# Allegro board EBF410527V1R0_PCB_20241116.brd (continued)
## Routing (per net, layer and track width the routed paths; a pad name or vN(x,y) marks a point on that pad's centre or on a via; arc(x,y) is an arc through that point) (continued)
VCC3V3_SD: length 8.9
  TOP w0.305: 19.44,46.79 20.02,47.37 21.36,47.37 21.98,47.99 R15.2 ; 19.44,46.79 19.44,46.83 18.9,47.37 17.45,47.37 16.9,46.82 C11.1 16.14,47.49 J2.4 ; 19.44,46.79 C10.1
VCC5V0_SYS: length 50.6
  TOP w0.254: v1(52.73,43.71) 52.82,43.81 U3.65 ; U3.66 v1(51.73,43.71) ; v1(69.81,12.27) 69.86,12.32 R12.1
  TOP w0.381: U17.6 65.53,47.09 65.91,47.47 67.23,47.47 67.61,47.09 67.61,43.65 C53.1 68.46,41.69 C52.1 v1(69.84,41.19)
  GND02 w0.254: v1(29.11,5.64) 29.11,7.19
  GND02 w0.508: J12.2 75.56,3.25 ; J12.2 74.56,2.25 ; J12.2 76.57,2.25 ; J12.4 74.03,2.25 ; J12.4 72.02,2.25 ; J12.4 73.03,3.25
  BOTTOM w0.254: R8.1 29.08,5.61 v1(29.11,5.64) ; v1(5.42,33.25) 5.84,33.67 5.84,48.64 6.53,49.33 16.59,49.33 C2.1 R6.1
  vias: v1(4.42,33.25) v1(4.42,32.25) v1(4.42,31.25) v1(4.45,27.96) v1(4.45,26.96) v1(4.45,25.96) v1(5.44,27.96) v1(51.73,42.71) v1(52.73,42.71) v1(67.54,51.51) v1(67.54,50.71) v1(67.54,49.91) v1(68.54,51.51) v1(69.84,41.99) v1(69.84,40.39) v1(70.64,41.19) v1(72.35,7.3) v1(73.35,7.3) v1(74.35,7.3) v1(75.35,9.3) v1(75.35,8.3) v1(75.35,7.3)
VCC_1V8: length 100.7
  TOP w0.254: 51.45,41.57 v1(51.45,31.72) ; 51.45,41.57 49.52,43.49 U3.68 ; 51.45,41.57 52.01,42.14 55.5,42.14 v1(56.57,41.07) ; v1(70.74,32) 70.74,32.26 72.13,33.65 v1(72.13,34.95) 72.14,34.96 72.14,36.65 70.64,38.15 70.64,39.67 71.31,40.35 71.31,42.19 70.48,43.02 70.48,44.04 69.47,45.06 R79.1 R80.1 ; R94.2 79.38,49.28 v1(82.42,49.28)
  GND02 w0.254: v1(72.13,34.95) 69.69,37.39 63.07,37.39 61.09,39.37 60.25,39.37 59.66,39.95 58.7,39.95 57.58,41.07 v1(56.57,41.07)
  BOTTOM w0.203: C12.1 47.11,33.51 U4.12
  BOTTOM w0.254: R33.1 v1(51.45,31.72) ; R33.1 50.77,30.63 R35.1 51.51,29.89 51.51,28.02 R22.1 ; R33.1 R31.1 R29.1 50.18,34.59 48.19,34.59 C12.1 ; v1(70.74,32) 73.53,32 74.17,31.37 81.15,31.37 82.42,32.64 v1(82.42,49.28)
VCC_3V3: length 239.2
  TOP w0.254: R74.1 v1(18.57,3.29) ; R75.1 v1(18.87,16.26)
  TOP w0.305: R15.1 C9.1 v1(23.75,49.15)
  TOP w0.508: J12.17 56.47,6.01 59.25,6.01 59.72,6.48 59.72,9.5 60.07,9.86 61.75,9.86 62.18,10.29 62.18,12.42 62.66,12.9 64.18,12.9
  GND02 w0.254: 20.52,6.53 25.7,6.53 26.64,5.59 26.64,2.18 27.07,1.76 v1(27.22,1.76) ; 20.52,6.53 19.58,5.59 19.58,3.71 19.17,3.29 v1(18.57,3.29) ; 20.52,6.53 19.43,7.62 19.43,15.71 v1(18.87,16.26) 13.58,16.26 13.03,16.81 13.03,18.47 12.57,18.92 2.21,18.92 1.7,19.43 1.7,36.17 2.34,36.8 v1(4.98,36.8)
  GND02 w0.381: v1(25.55,31.25) 22.32,31.25 v1(20.17,33.41) 18.05,33.41 14.66,36.8 v1(4.98,36.8)
  BOTTOM w0.203: C13.1 46.71,33.88 U4.11 ; C1.1 38.25,33.37 U1.9 ; C14.1 46.46,27.29 U5.21
  BOTTOM w0.254: v1(41.04,21.45) C19.1 R45.1 ; R36.1 v1(42.7,30.58) ; C13.1 v1(46.58,34.8) ; R64.1 R65.1 23.88,49.28 v1(23.75,49.15) ; C7.1 68.08,13.67 C8.1 R10.1 C5.1 ; v1(49.78,29.08) R28.1 R27.1 ; v1(47.75,29.08) 47.53,29.08 47.17,28.73 47.17,28 C14.1 ; R30.1 v1(42.7,34.01) 39.9,34.01 R1.1 39.29,34.62 38.16,34.62 C1.1 ; R9.1 32.55,4.94 33.12,4.37 33.12,2.46 32.84,2.18 27.64,2.18 v1(27.22,1.76) ; R34.1 v1(42.7,31.72) ; R32.1 v1(42.7,32.87) ; R26.1 v1(43.43,29.08)
  BOTTOM w0.305: v1(4.98,36.8) 4.98,49.15 5.89,50.06 21.56,50.06 22.17,49.45 23.44,49.45 v1(23.75,49.15)
  BOTTOM w0.381: 32.12,27.41 32.12,24.6 31.32,23.8 ; 32.12,27.41 J4.24 ; 32.12,27.41 C33.1 32.14,28.89 32.56,29.31 34.47,29.31 35.23,30.07 35.23,34.26 34.8,34.7 31.97,34.7 31.46,35.2 v1(31.46,36.25) ; J4.2 30.94,15.41 31.32,15.79 31.32,23.8 ; 31.32,23.8 30.86,24.26 28.32,24.26 25.55,27.03 v1(25.55,31.25) ; C35.1 32.14,37.62 C34.1 32.01,38.61 J4.52 ; J4.39 v1(20.17,33.41)
  BOTTOM w0.508: v1(65.37,14.73) 65.37,8.78 66.42,7.72 70.71,7.72 71.98,6.45 73.9,6.45 J12.1
  vias: v1(31.45,37.2) v1(65.37,16.33) v1(65.37,15.53) v1(66.17,16.33) v1(66.17,15.53) v1(66.17,14.73) v1(70.13,34.95) v1(70.13,33.95) v1(71.13,34.95) v1(71.13,33.95)
VCC_3V3_EN: length 52.6
  TOP w0.152: U3.70 47.33,43.28 47.6,43 48.84,43 49.96,41.88 49.96,30.89 51.16,29.69 51.16,20.77 v1(51.92,20.01) ; R14.1 69.86,16.76 v1(69.57,17.04)
  BOTTOM w0.152: v1(51.92,20.01) 52.82,20.9 69.37,20.9 69.57,20.7 v1(69.57,17.04)
VCC_WLAN: length 8.7
  TOP w0.508: U10.6 62.32,32.09 62,32.41 62,35.3 62.51,35.81 C28.1 ; C29.1 C28.1 ; C28.1 63.13,35.81 Q2.3
VDD_LCD_3V3: length 30.9
  TOP w0.254: v1(23.77,48.13) 24.87,48.13 26.59,49.86 26.59,53.82 27.38,54.61 46.38,54.61 47.66,53.33
  BOTTOM w0.254: R63.1 24.31,47.24 23.77,47.78 v1(23.77,48.13)
  vias: v1(48.11,53.05) v1(49.06,53.05)
VDD_LCD_5V:
  vias: v1(49.05,52.12) v1(49.06,51.16)
CAM0_NRST: length 58.2
  TOP w0.152: v1(66.22,30.02) 66.76,29.48 66.76,24.74 66.45,24.43 62.14,24.43 60.76,23.05 v1(60.76,22.58)
  BOTTOM w0.152: v1(60.76,22.58) 51.97,22.58 50.41,24.14 U5.2 ; J5.22 49.47,48.18 49.77,47.88 52.02,47.88 52.27,48.13 52.73,48.13 53.06,47.8 53.06,46.34 54.76,44.64 54.76,42.3 55.21,41.86 55.21,38.34 57.1,36.44 57.1,34.09 58.33,32.86 58.33,31.57 60.61,29.29 62.26,29.29 62.99,30.02 v1(66.22,30.02)
CAM0_PWDN: length 56.1
  TOP w0.152: v1(67.22,30.02) 67.22,24.53 66.66,23.98 62.33,23.98 61.73,23.38 61.73,22.61 v1(61.76,22.58)
  BOTTOM w0.152: v1(61.76,22.58) 61.68,22.58 61.2,23.06 52.25,23.06 50.67,24.64 U5.1 ; J5.15 52.97,48.58 53.52,48.03 53.52,46.53 55.22,44.83 55.22,42.52 55.66,42.07 55.66,38.53 57.56,36.63 57.56,34.28 58.79,33.05 58.79,31.76 60.78,29.77 62.03,29.77 62.87,30.61 66.63,30.61 v1(67.22,30.02)
CAM0_PWR_EN: length 8.7
  TOP w0.152: U3.59 60.95,42.16 62.28,43.48 66.13,43.48 v1(66.19,43.42)
  BOTTOM w0.152: v1(66.19,43.42) 66.59,43.81 R59.1
CAM1_NRST: length 40
  TOP w0.152: v1(46.57,37.44) 46.57,36.91 46.09,36.43 46.09,34.6 46.38,34.31 46.38,29.87 47.27,28.98 47.27,25.63 49.58,23.32 v1(49.58,23.14)
  BOTTOM w0.152: U5.4 v1(49.58,23.14) ; J6.22 31.27,48.67 31.58,48.36 33.68,48.36 35.48,46.56 35.48,42.43 39.94,37.98 46.04,37.98 v1(46.57,37.44)
CAM1_PWDN: length 40.6
  TOP w0.152: v1(50.58,23.14) 50.58,29.38 50.16,29.79 48.01,29.79 47.5,30.3 47.5,31.85 46.84,32.51 46.84,33.99 47.57,34.72 v1(47.57,37.44)
  BOTTOM w0.152: J6.15 34.77,48.03 35.97,46.84 35.97,42.6 40.13,38.43 46.58,38.43 v1(47.57,37.44) ; v1(50.58,23.14) 50.08,23.64 U5.3
CAM1_PWR_EN: length 18.1
  TOP w0.152: U3.58 57.84,41.06 57.53,41.36 57.53,43.48 58.14,44.09 58.14,47.19 57.86,47.47 57.15,47.47 56.97,47.65 v1(52.52,47.65)
  BOTTOM w0.152: v1(52.52,47.65) 52.3,47.42 49.21,47.42 R61.1
DBG_DN: length 68.1
  TOP w0.157: v1(36.78,32.36) 37.63,32.36 37.97,32.7 37.97,34.26 38.81,35.11 v1(38.81,35.59)
  BOTTOM w0.157: U1.7 37.11,32.05 36.8,32.36 v1(36.78,32.36) ; v1(38.81,35.59) 39.09,35.86 50.62,35.86 52.47,34.02 52.47,25.15 53.11,24.51 72.52,24.51 72.9,24.13 72.9,19.34 73.42,18.82 76.05,18.82 76.71,18.16 76.71,16.13 77.6,15.24 77.6,12.57 78.03,12.14 79.74,12.14 80.07,11.81 R3.2
DBG_DP: length 70.4
  TOP w0.157: v1(38.81,36.55) 38.81,36.3 39.31,35.8 39.31,35.09 38.33,34.11 38.33,32.7 38.64,32.38 v1(39.52,32.38)
  BOTTOM w0.157: U1.1 39.36,32.05 39.52,32.21 v1(39.52,32.38) ; R2.2 80.07,12.83 79.74,12.5 78.18,12.5 77.96,12.72 77.96,15.39 77.07,16.28 77.07,18.31 76.2,19.18 73.57,19.18 73.26,19.49 73.26,24.28 72.67,24.87 53.26,24.87 52.83,25.3 52.83,34.17 50.77,36.23 44.4,36.23 arc(44.31,36.26) 44.28,36.35 arc(44.24,36.44) 44.15,36.47 43.77,36.47 arc(43.68,36.44) 43.65,36.35 arc(43.61,36.26) 43.52,36.23 43.14,36.23 arc(43.05,36.26) 43.02,36.35 arc(42.98,36.44) 42.89,36.47 42.51,36.47 arc(42.42,36.44) 42.39,36.35 arc(42.35,36.26) 42.26,36.23 41.88,36.23 arc(41.79,36.26) 41.76,36.35 arc(41.72,36.44) 41.63,36.47 41.25,36.47 arc(41.16,36.44) 41.13,36.35 arc(41.09,36.26) 41,36.23 40.62,36.23 arc(40.53,36.26) 40.5,36.35 arc(40.46,36.44) 40.37,36.47 39.99,36.47 arc(39.91,36.44) 39.87,36.35 arc(39.83,36.26) 39.74,36.23 39.14,36.23 v1(38.81,36.55)
DBG_RX: length 4.3
  TOP w0.152: R89.1 Z2.1 73.19,45.44 73.69,45.44 74.17,44.96 J13.2
DBG_TX: length 3.4
  TOP w0.152: Z1.1 R88.1 76.71,45.98 J13.3
DC_EN: length 3.8
  TOP w0.152: R14.2 R12.2 71.31,12.63 U2.1
DISP: length 8.5
  TOP w0.152: v1(26.59,47.22) 26.62,47.24 30.11,47.24 31.21,48.34 31.95,48.34 32.52,48.9 J7.7
  BOTTOM w0.152: v1(26.59,47.22) 26.57,47.24 R63.2
DM1: length 10.4
  TOP w0.157: R37.1 17.46,27.61 17.46,28.47 17.53,28.54 U9.2 U9.9 17.53,30.64 17.46,30.71 17.46,31.03 17.1,31.39 16.22,31.39 15.75,30.92 15.75,28.83 15.41,28.49 14.32,28.49 J3.2
DM2: length 16.2
  TOP w0.157: R40.1 18.96,28.14 18.96,28.47 19.03,28.54 U9.5 U9.6 19.03,30.64 18.96,30.71 18.96,31.25 17.88,32.33 15.39,32.33 14.76,31.71 14.76,30.89 14.6,30.73 12.47,30.73 11.99,30.25 11.99,28.8 11.68,28.49 11.32,28.49 J3.8
DP1: length 10.4
  TOP w0.157: R38.1 17.1,28.14 17.1,28.47 17.03,28.54 U9.1 U9.10 17.03,30.64 17.1,30.71 17.1,30.88 16.95,31.03 16.37,31.03 16.11,30.77 16.11,28.68 15.56,28.13 13.81,28.13 13.5,27.83 J3.3
DP2: length 15.6
  TOP w0.157: R42.1 18.6,27.61 18.6,28.47 18.53,28.54 U9.4 U9.7 18.53,30.64 18.6,30.71 18.6,31.1 17.73,31.97 15.53,31.97 15.12,31.56 15.12,30.74 14.75,30.37 12.62,30.37 12.35,30.1 12.35,28.65 11.83,28.13 10.83,28.13 10.5,27.8 J3.9
FEPHY_LINK: length 40
  TOP w0.152: U3.102 21.67,31.15 21.06,30.55 21.06,28.3 20.57,27.81 20.57,24.23 20.24,23.9 20.24,12.62 v1(19.96,12.34)
  GND02 w0.152: v1(19.96,12.34) 20.45,11.86 20.45,8.81 21.95,7.32 26.21,7.32 27.28,6.25 28.04,6.25 28.57,5.71 28.57,4.39 28.9,4.07 v1(31.68,4.07)
  BOTTOM w0.152: R78.1 31.55,3.95 v1(31.68,4.07)
FEPHY_RXN: length 37.5
  TOP w0.124: v1(51.81,7.68) 52.11,7.98 52.11,8.39 51.73,8.78 U3.25
  BOTTOM w0.124: v1(51.81,7.68) 52.11,7.98 52.11,8.27 52.43,8.59 53.25,8.59 53.57,8.27 53.57,7.34 53.12,6.89 51.14,6.89 50.61,6.35 47.6,6.35 47.3,6.65 24.32,6.65 23.87,7.1 23.14,7.1 22.8,6.76 R70.1
FEPHY_RXP: length 35.9
  TOP w0.124: U3.26 52.82,8.81 52.44,8.42 52.44,7.98 v1(52.74,7.68)
  BOTTOM w0.124: v1(52.74,7.68) 52.69,7.68 52.44,7.93 52.44,8.13 52.56,8.26 53.11,8.26 53.24,8.13 53.24,7.47 52.98,7.21 51.01,7.21 50.47,6.68 47.74,6.68 47.43,6.98 24.45,6.98 24.01,7.43 23.14,7.43 22.8,7.77 R71.1
FEPHY_SPD: length 35
  TOP w0.152: U3.103 22.17,30.06 21.54,29.42 21.54,28.07 20.88,27.41 20.88,24.08 20.55,23.75 20.55,11.93 v1(19.96,11.34)
  GND02 w0.152: v1(28.08,4.07) 27.51,4.65 27.51,5.54 26.09,6.96 21.82,6.96 20.09,8.69 20.09,11.22 v1(19.96,11.34)
  BOTTOM w0.152: R76.1 27.95,3.95 v1(28.08,4.07)
FEPHY_TXN: length 38.5
  TOP w0.124: v1(49.81,7.68) 49.47,7.35 49.47,6.89 49.68,6.68 55.09,6.68 55.41,7.01 55.41,8.1 55.29,8.23 55.15,8.23 55.03,8.35 U3.28
  BOTTOM w0.124: R72.1 22.8,9.8 23.14,9.46 24.02,9.46 25.16,8.32 46.67,8.32 46.86,8.51 49.16,8.51 49.47,8.19 49.47,7.93 49.72,7.68 v1(49.81,7.68)
FEPHY_TXP: length 39
  TOP w0.124: v1(48.81,7.68) 49.15,7.35 49.15,6.75 49.55,6.35 55.22,6.35 55.74,6.87 55.74,8.1 55.86,8.23 56,8.23 56.13,8.35 U3.29
  BOTTOM w0.124: v1(48.81,7.68) 48.9,7.68 49.15,7.93 49.15,8.05 49.02,8.18 46.99,8.18 46.81,7.99 25.03,7.99 23.89,9.13 23.14,9.13 22.8,8.79 R73.1
GPIO0_A0: length 60.1
  TOP w0.152: v1(35.14,13.18) 34.65,13.67 34.65,16.28 29.67,21.25 U3.111
  BOTTOM w0.152: v1(35.14,13.18) 42.09,13.18 43.64,14.73 59.28,14.73 59.94,14.07 59.94,6.76 61.44,5.26 61.44,3.86 61.65,3.66 66.82,3.66 J12.7
GPIO0_A1: length 52.1
  TOP w0.152: v1(34.14,14.18) 34.14,15.77 29.76,20.15 U3.112
  BOTTOM w0.152: J12.11 62.5,4.79 60.3,6.99 60.3,14.3 59.56,15.04 43.32,15.04 41.97,13.69 34.63,13.69 v1(34.14,14.18)
GPIO0_A2: length 49.9
  TOP w0.152: v1(34.14,13.18) 33.48,13.84 33.48,15.37 29.79,19.06 U3.113
  BOTTOM w0.152: J12.13 59.61,5.5 59.61,13.74 58.93,14.43 43.92,14.43 42.19,12.7 34.62,12.7 v1(34.14,13.18)
GPIO0_A4: length 51
  TOP w0.152: v1(30.64,12.12) 30.64,16.04 29.83,16.85 U3.115
  BOTTOM w0.152: v1(30.64,12.12) 30.64,11.4 30.96,11.07 32.26,11.07 32.89,11.71 43.21,11.71 44.22,12.73 48.84,12.73 49.93,13.82 58.55,13.82 58.95,13.41 58.95,5.95 J12.15
GPIO0_A5: length 54.3
  TOP w0.152: U3.116 24.7,15.76 25.25,16.31 29.34,16.31 29.64,16 v1(29.64,12.12)
  BOTTOM w0.152: J12.16 59.28,3.74 59.28,13.54 58.7,14.12 49.81,14.12 48.94,13.26 44.07,13.26 42.9,12.09 32.59,12.09 32,11.51 31.46,11.51 31.16,11.81 31.16,12.35 30.91,12.6 30.12,12.6 v1(29.64,12.12)
GPIO5_P1_0: length 28.3
  TOP w0.152: v1(53.7,11.18) 51.4,13.48 51.4,19.45 50.92,19.93 v1(50.92,20.01)
  BOTTOM w0.152: J12.18 56.34,3.34 56.34,11.35 56.03,11.66 54.18,11.66 v1(53.7,11.18) ; v1(50.92,20.01) 46.61,20.01 46.46,20.16 U5.10
GPIO5_P1_1: length 29.8
  TOP w0.152: v1(51.92,19.01) 51.92,13.96 v1(54.7,11.18)
  BOTTOM w0.152: U5.11 45.96,19.79 46.27,19.49 51.44,19.49 v1(51.92,19.01) ; v1(54.7,11.18) 55.4,10.48 55.4,6.55 54.2,5.36 54.2,3.66 53.9,3.35 52.22,3.35 51.12,2.25 J12.22
GPIO5_P1_2: length 34.3
  TOP w0.152: v1(50.92,19.01) 50.92,12.96 v1(52.7,11.18)
  BOTTOM w0.152: v1(50.92,19.01) 45.77,19.01 45.46,19.31 U5.12 ; J12.26 45.88,2.25 46.91,3.28 48.49,3.28 48.92,3.71 51.05,3.71 51.51,4.17 51.51,5.56 51.82,5.87 53.54,5.87 54.56,6.88 54.56,9.7 54.25,10.01 53.07,10.01 52.7,10.38 v1(52.7,11.18)
HUB_3V3: length 17
  BOTTOM w0.254: R41.1 R39.1 R43.1 41.15,27.68 41.15,25.03 C21.1 ; U6.1 39.5,20.47 39.73,20.24 40.5,20.24 41.32,19.42 C20.1 42.39,20.03 42.39,22.88 R45.2 C21.1 ; C21.1 41.16,24.39 40.91,24.14 U6.20
I2C3_SCL_LT: length 85.6
  TOP w0.152: v1(45.11,31.78) 44.45,31.11 v1(44.45,29.08)
  GND02 w0.152: v1(45.11,31.78) 44.73,32.16 44.04,32.16 43.64,32.56 43.64,38.43 43.13,38.94 43.13,43.04 v1(42.54,43.64)
  BOTTOM w0.152: J6.6 39.27,48.51 40.36,47.42 40.36,45.03 41.74,43.65 42.52,43.65 v1(42.54,43.64) ; J12.5 69.33,5.94 62.43,5.94 61.75,6.63 61.75,12.03 62.06,12.33 63.8,12.33 64.11,12.64 64.11,17.35 62.18,19.28 60.43,19.28 59.36,18.21 44.17,18.21 43.87,18.52 43.87,25.53 42.49,26.9 42.49,29.72 42.19,30.02 42.19,30.96 42.42,31.2 43.89,31.2 R34.2 44.47,31.78 v1(45.11,31.78) 45.19,31.85 U4.8 ; R23.1 v1(44.45,29.08)
I2C3_SCL_M2: length 22.1
  TOP w0.152: U3.75 41.82,43.42 43.64,41.61 48.06,41.61 48.67,41 48.67,34.34 48.21,33.88 48.21,32.16 v1(49.06,31.31)
  BOTTOM w0.152: R33.2 49.48,31.72 v1(49.06,31.31) 48.92,31.45 U4.3
I2C3_SDA_LT: length 86.4
  GND02 w0.152: v1(45.11,30.78) 45.59,31.26 45.59,32.21 45.16,32.64 44.35,32.64 44.09,32.9 44.09,38.64 43.54,39.19 v1(43.54,43.64)
  BOTTOM w0.152: R36.2 43.88,30.05 43.1,30.05 42.8,29.74 42.8,27.02 44.17,25.65 44.17,18.82 44.48,18.52 59.11,18.52 60.25,19.66 62.23,19.66 64.41,17.47 64.41,12.33 64.11,12.03 62.53,12.03 62.23,11.72 62.23,6.86 62.71,6.38 70.59,6.38 72.18,4.79 J12.3 ; R36.2 44.61,30.78 v1(45.11,30.78) 45.31,30.98 45.31,31.29 45.47,31.45 U4.7 ; R36.2 45.47,29.53 R24.1 ; J6.5 39.77,48.49 40.69,47.57 40.69,45.19 41.64,44.23 42.94,44.23 v1(43.54,43.64)
I2C3_SDA_M2: length 25.5
  TOP w0.152: U3.76 40.73,43.55 43.13,41.15 47.7,41.15 48.23,40.61 48.23,34.57 47.19,33.53 47.19,32.79 47.9,32.08 47.9,30.74 48.34,30.31 v1(49.06,30.31)
  BOTTOM w0.152: U4.4 47.11,30.64 47.26,30.49 48.88,30.49 v1(49.06,30.31) 49.36,30.61 R35.2
I2C4_SCL_LT: length 162.9
  TOP w0.152: v1(45.54,51.95) 45.67,52.08 45.67,53.44 45.21,53.9 30.73,53.9 30.3,53.47 30.3,51.48 29.52,50.7 J7.1 ; J12.28 43.63,3.33 61.47,3.33 61.77,3.63 61.77,6.38 61.27,6.88 v1(61.27,6.92) ; v1(60.78,17.77) 61.26,18.25 61.26,20.47 63.02,22.23 68.63,22.23 68.94,22.53 68.94,29.28 v1(69.66,30)
  BOTTOM w0.152: v1(61.27,6.92) 60.76,7.43 60.76,12.74 61.06,13.04 63.18,13.04 63.5,13.36 63.5,17.1 62.82,17.77 v1(60.78,17.77) 60.76,17.77 60.54,17.55 43.79,17.55 43.26,18.08 43.26,25.27 41.88,26.64 41.88,29.08 41.43,29.54 41.43,33.15 41.76,33.48 43.88,33.48 R30.2 45.03,33.4 46.1,33.4 46.31,33.19 U4.10 ; v1(69.66,30) 69.17,29.51 68.4,29.51 66.8,31.11 62.59,31.11 62.15,31.55 62.15,43.4 61.61,43.94 60.55,43.94 59.72,44.78 59.72,46.33 57.47,48.57 J5.6 57.47,50.19 57.32,50.34 45.47,50.34 45.14,50.68 45.14,51.55 v1(45.54,51.95)
I2C4_SCL_M2: length 18.9
  TOP w0.152: U3.72 45.12,42.77 45.43,42.47 48.74,42.47 49.5,41.71 49.5,33.75 v1(49.06,33.31)
  BOTTOM w0.152: U4.1 48,32.25 48.26,32.51 48.26,33.02 48.55,33.31 v1(49.06,33.31) R29.2
I2C4_SDA_LT: length 154.9
  TOP w0.152: J12.27 43.62,3.71 61.05,3.71 61.35,4.01 61.35,5.88 60.79,6.45 60.79,7.43 v1(61.27,7.92) ; v1(68.66,30) 68.53,29.87 68.53,22.83 68.22,22.53 62.79,22.53 60.78,20.52 v1(60.78,18.77) ; v1(45.62,50.95) 45.06,51.51 45.06,52.3 45.26,52.5 45.26,53.24 44.96,53.54 31.06,53.54 30.68,53.16 30.68,51.29 30.02,50.62 J7.2
  BOTTOM w0.152: U4.9 45.42,32.25 45.21,32.46 44.82,32.46 R32.2 43.86,32.31 42.11,32.31 41.81,32 41.81,29.79 42.19,29.41 42.19,26.77 43.56,25.4 43.56,18.29 43.99,17.86 59.84,17.86 60.76,18.77 v1(60.78,18.77) 62.26,18.77 63.8,17.22 63.8,13.04 63.46,12.7 61.57,12.7 61.27,12.4 v1(61.27,7.92) ; v1(45.62,50.95) 45.9,50.67 57.82,50.67 57.97,50.52 J5.5 57.97,48.55 60.17,46.35 60.17,44.91 60.68,44.4 61.72,44.4 62.6,43.52 62.6,31.91 62.92,31.6 67.06,31.6 v1(68.66,30)
I2C4_SDA_M2: length 20.2
  TOP w0.152: U3.73 44.03,42.32 44.33,42.01 48.39,42.01 49.05,41.35 49.05,34.06 48.54,33.55 48.54,32.83 v1(49.06,32.31)
  BOTTOM w0.152: R31.2 49.62,32.87 v1(49.06,32.31) 48.61,31.85 U4.2
LCD_INT: length 61.2
  TOP w0.152: J7.3 30.52,49.23 29.96,48.67 27.33,48.67 v1(27.08,48.92) ; U3.6 30.82,10.59 31.13,10.9 32.99,10.9 33.83,11.73 36.17,11.73 36.6,12.17 36.6,16.87 30.56,22.91 30.56,30.65 30.25,30.96 v1(26.94,30.96)
  BOTTOM w0.152: R65.2 26.72,49.28 v1(27.08,48.92) 27.43,48.57 27.43,45.9 29.35,43.98 29.83,43.98 30.14,43.66 30.14,43.01 30.71,42.44 30.71,40.16 30.35,39.8 27.58,39.8 27.28,39.49 27.28,31.3 v1(26.94,30.96)
LCD_PWM_BL: length 60.5
  TOP w0.152: v1(25.98,46.53) 25.98,47.47 26.29,47.78 30.17,47.78 31.09,48.69 31.7,48.69 32.02,49.01 J7.6 ; v1(26.07,37.76) 26.37,37.46 26.37,29.77 26.67,29.46 29.31,29.46 29.62,29.16 29.62,22.2 35.71,16.1 35.71,12.9 35.41,12.6 33.45,12.6 32.49,11.63 29.62,11.63 28.63,10.64 U3.4
  GND02 w0.152: v1(26.07,37.76) 26.07,37.81 25.35,38.53 23.37,38.53 22.94,38.96 22.94,41.12 24.71,42.9 24.71,44.48 25.98,45.75 v1(25.98,46.53)
LCD_RST: length 61.1
  TOP w0.152: v1(26.94,29.96) 29.79,29.96 30.1,29.65 30.1,22.58 36.12,16.56 36.12,12.47 35.81,12.17 33.63,12.17 32.72,11.25 30.3,11.25 29.73,10.68 U3.5 ; J7.4 31.02,49.05 30.23,48.26 v1(26.39,48.26)
  BOTTOM w0.152: R64.2 v1(26.39,48.26) 27.1,47.55 27.1,45.77 29.14,43.73 29.14,43.1 30.35,41.88 30.35,40.46 30,40.1 27.33,40.1 26.95,39.72 26.95,32.08 26.42,31.55 26.42,30.48 v1(26.94,29.96)
LINEOUT: length 56.1
  TOP w0.203: U3.89 v1(26.42,43.66) ; v1(32.27,51) 32.27,52.24 32.94,52.91 43.74,52.91 44.27,52.37 44.27,51.28 v1(44.63,50.93) ; C54.1 64.27,39.44 63.58,40.13 63.58,42.24 v1(63.32,42.49)
  GND02 w0.203: v1(26.42,43.66) 26.53,43.66 27.34,44.48 28.32,44.48 28.65,44.81 28.65,49.33 30.86,51.54 31.74,51.54 v1(32.27,51) ; v1(63.32,42.49) 62.31,42.49 60.99,43.81 59.21,43.81 57.28,45.75 56.79,45.75 54.84,47.7 53.77,47.7 52.55,48.92 46.94,48.92 46.18,49.68 45.16,49.68 44.63,50.22 v1(44.63,50.93)
MICIN0_N: length 78.9
  TOP w0.203: C50.2 R83.1 ; C50.2 v1(74.56,47.75) ; C50.2 74.83,48.79 74.83,49.21 73.8,50.24 J9.2
  TOP w0.254: U3.96 v1(25.07,37.76)
  GND02 w0.203: v1(25.07,37.76) 24.78,37.47 23.37,37.47 22.32,38.52 22.32,41.34 24.1,43.12 24.1,44.78 25.17,45.85 25.17,46.81 25.87,47.51 25.87,48.48 27.99,50.6 27.99,52.78 28.4,53.19 32.36,53.19 32.91,53.74 49.33,53.74 50.9,52.17 55.6,52.17 59.11,48.67 59.11,46.71 60.02,45.8 68.45,45.8 70.79,48.13 74.18,48.13 v1(74.56,47.75)
MICIN0_P: length 81
  TOP w0.203: C50.1 v1(75.56,47.75) ; C50.1 75.23,48.84 75.23,49.35 75.05,49.54 J9.1 ; C50.1 R81.1
  TOP w0.254: U3.97 v1(25.07,36.65)
  GND02 w0.203: v1(25.07,36.65) 25.07,36.66 24.66,37.07 23.21,37.07 21.92,38.35 21.92,41.5 23.7,43.28 23.7,44.91 24.8,46.01 24.8,47 25.52,47.72 25.52,48.63 27.64,50.74 27.64,52.93 28.29,53.59 32.22,53.59 32.74,54.1 49.48,54.1 51,52.58 55.7,52.58 59.46,48.82 59.46,46.88 60.19,46.15 68.28,46.15 70.62,48.49 74.82,48.49 v1(75.56,47.75)
MICIN1_N: length 73.5
  TOP w0.203: J10.2 64.95,49.06 C51.2 ; C51.2 R84.1 ; C51.2 63.84,47.96 62.05,47.96 61.03,46.93 v1(60.82,46.93)
  TOP w0.254: U3.99 v1(25.55,34.46)
  GND02 w0.203: v1(60.82,46.93) 61.03,47.14 61.03,47.71 60.4,48.34 60.4,49.69 56.5,53.59 51.59,53.59 50.44,54.74 32.11,54.74 31.65,54.28 27.61,54.28 26.87,53.54 26.87,50.98 24.79,48.9 24.79,47.93 24.1,47.24 24.1,46.33 23.09,45.31 23.09,43.56 21.31,41.78 21.31,37.44 24.61,34.14 25.34,34.14 25.55,34.35 v1(25.55,34.46)
MICIN1_P: length 75.6
  TOP w0.203: J10.1 66.2,50.22 65.4,49.42 C51.1 ; C51.1 64.48,47.6 62.37,47.6 61.82,47.04 v1(61.82,46.93) ; C51.1 R82.1
  TOP w0.254: U3.100 v1(25.55,33.36)
  GND02 w0.203: v1(25.55,33.36) 25.55,33.46 25.23,33.78 24.47,33.78 20.95,37.29 20.95,41.93 22.73,43.71 22.73,45.49 23.72,46.48 23.72,47.36 24.41,48.05 24.41,49.05 26.49,51.14 26.49,53.7 27.45,54.66 31.49,54.66 31.92,55.1 50.59,55.1 51.71,53.98 56.64,53.98 60.76,49.86 60.76,48.49 61.41,47.84 61.41,47.34 v1(61.82,46.93)
MIPI_CSI_RX_CLK0N: length 22.7
  TOP w0.124: U3.49 59.78,31.15 60.19,31.56 60.67,31.56 v1(60.92,31.31)
  BOTTOM w0.124: v1(60.92,31.31) 60.62,31.61 60.28,31.61 59.64,32.26 59.64,33.4 58.41,34.63 58.41,42.45 57.23,43.64 57.23,45.06 55.56,46.73 55.56,48.52 55.47,48.61 J5.10
MIPI_CSI_RX_CLK0P: length 22.7
  TOP w0.124: U3.50 59.82,32.25 60.19,31.89 60.57,31.89 v1(60.92,32.24)
  BOTTOM w0.124: J5.9 55.97,48.61 55.89,48.52 55.89,48.24 arc(55.92,48.17) 55.99,48.14 arc(56.05,48.11) 56.08,48.04 56.08,47.74 arc(56.05,47.67) 55.99,47.64 arc(55.92,47.61) 55.89,47.54 55.89,46.86 56.28,46.47 arc(56.37,46.43) 56.47,46.47 56.47,46.47 arc(56.56,46.51) 56.65,46.47 56.82,46.3 arc(56.86,46.21) 56.82,46.12 arc(56.78,46.02) 56.82,45.93 57.55,45.2 57.55,43.77 58.74,42.59 58.74,34.76 59.97,33.53 59.97,32.39 60.42,31.94 60.67,31.94 60.92,32.19 v1(60.92,32.24)
MIPI_CSI_RX_CLK1N: length 45.3
  TOP w0.124: v1(56.4,25.65) 56.77,25.28 56.77,22.13 57.26,21.64 57.67,21.64 57.8,21.52 57.8,21.38 57.92,21.25 U3.40
  BOTTOM w0.124: v1(56.4,25.65) 56.68,25.94 56.68,27.04 57.12,27.48 58.06,27.48 58.18,27.61 58.18,28.17 58.06,28.3 57.38,28.3 57.02,28.65 57.02,29.49 55.98,30.53 55.98,31.89 54.71,33.16 54.71,35.07 48.69,41.09 40.69,41.09 37.45,44.34 37.45,48.44 37.27,48.61 J6.10
MIPI_CSI_RX_CLK1P: length 45.1
  TOP w0.124: U3.41 57.92,22.36 57.8,22.23 57.8,22.09 57.67,21.97 57.4,21.97 57.1,22.27 57.1,25.33 57.4,25.63 v1(57.4,25.63)
  BOTTOM w0.124: v1(57.4,25.63) 57.35,25.63 57.01,25.97 57.01,26.9 57.26,27.15 58.19,27.15 58.51,27.47 58.51,28.31 58.19,28.63 57.51,28.63 57.35,28.79 57.35,29.62 56.31,30.67 56.31,32.02 55.04,33.29 55.04,35.21 48.82,41.42 40.82,41.42 37.77,44.47 37.77,44.82 arc(37.8,44.89) 37.87,44.92 arc(37.94,44.95) 37.97,45.02 37.97,45.32 arc(37.94,45.39) 37.87,45.42 arc(37.8,45.45) 37.77,45.52 37.77,45.82 arc(37.8,45.89) 37.87,45.92 arc(37.94,45.95) 37.97,46.02 37.97,46.31 arc(37.94,46.39) 37.87,46.41 arc(37.8,46.44) 37.77,46.51 J6.9
MIPI_CSI_RX_D0N: length 22.3
  TOP w0.124: U3.55 58.33,37.76 57.95,38.14 57.5,38.14 57.35,37.99 57.35,35.11 57.03,34.79 56.55,34.79 56.24,35.11 56.24,38.53 56.9,39.19 56.9,39.46 v1(56.6,39.76)
  BOTTOM w0.124: v1(56.6,39.76) 56.9,40.06 56.9,40.47 57.15,40.73 57.15,41.39 56.43,42.12 56.43,42.6 56.21,42.82 56.21,45 54.56,46.65 54.56,48.52 54.47,48.61 J5.12
MIPI_CSI_RX_D0P: length 22.3
  TOP w0.124: v1(57.53,39.76) 57.23,39.46 57.23,39.06 56.57,38.4 56.57,35.24 56.69,35.12 56.9,35.12 57.02,35.24 57.02,38.13 57.36,38.47 57.98,38.47 58.36,38.85 U3.56
  BOTTOM w0.124: J5.11 54.97,48.61 54.89,48.52 54.89,48.23 arc(54.92,48.16) 54.99,48.13 arc(55.06,48.1) 55.09,48.03 55.09,47.73 arc(55.06,47.66) 54.99,47.63 arc(54.92,47.6) 54.89,47.53 54.89,46.79 56.54,45.14 56.54,44.68 arc(56.58,44.59) 56.67,44.56 arc(56.76,44.52) 56.79,44.43 56.79,44.19 arc(56.76,44.1) 56.67,44.06 arc(56.58,44.02) 56.54,43.93 56.54,42.95 56.76,42.73 56.76,42.25 57.48,41.53 57.48,40.59 57.23,40.34 57.23,40.06 v1(57.53,39.76)
MIPI_CSI_RX_D1N: length 22.5
  TOP w0.124: v1(60.92,34.61) 60.67,34.86 60.13,34.86 59.73,34.46 U3.52
  BOTTOM w0.124: v1(60.92,34.61) 60.62,34.91 59.88,34.91 59.44,35.35 59.44,37.67 59.88,38.12 60.43,38.12 60.58,38.27 60.58,38.49 60.46,38.61 59.88,38.61 59.44,39.05 59.44,40.81 59.88,41.25 60.43,41.25 60.58,41.4 60.58,41.63 60.46,41.75 59.85,41.75 59.54,42.07 59.54,42.95 58.22,44.27 58.22,45.99 56.56,47.65 56.56,48.52 56.47,48.61 J5.8
MIPI_CSI_RX_D1P: length 22.5
  TOP w0.124: v1(60.92,35.54) 60.57,35.19 60.19,35.19 59.82,35.55 U3.53
  BOTTOM w0.124: v1(60.92,35.54) 60.62,35.24 60.01,35.24 59.76,35.49 59.76,37.54 60.01,37.79 60.57,37.79 60.91,38.13 60.91,38.62 60.59,38.94 60.01,38.94 59.76,39.19 59.76,40.68 60.01,40.93 60.57,40.93 60.91,41.27 60.91,41.76 60.59,42.08 59.99,42.08 59.87,42.2 59.87,43.09 58.54,44.41 58.54,44.95 arc(58.58,45.03) 58.66,45.07 arc(58.74,45.1) 58.78,45.18 58.78,45.45 arc(58.74,45.53) 58.66,45.56 arc(58.58,45.6) 58.54,45.68 58.54,46.13 57.86,46.81 arc(57.82,46.9) 57.86,46.98 arc(57.89,47.06) 57.86,47.15 57.67,47.33 arc(57.59,47.37) 57.51,47.33 arc(57.42,47.3) 57.34,47.33 56.89,47.79 56.89,48.52 56.97,48.61 J5.7
MIPI_CSI_RX_D2N: length 44.7
  TOP w0.124: v1(56.04,27.94) 56.34,28.24 57.67,28.24 57.8,28.12 57.8,27.98 57.92,27.85 U3.46
  BOTTOM w0.124: J6.12 36.27,48.61 36.36,48.52 36.36,47.76 36.65,47.46 36.65,43.13 40.01,39.78 48.58,39.78 53.59,34.77 53.59,30.63 53.91,30.31 54.74,30.31 54.87,30.19 54.87,29.94 54.74,29.81 53.91,29.81 53.59,29.5 53.59,26.73 54.06,26.26 54.87,26.26 55.24,26.63 55.24,28.01 55.48,28.24 55.74,28.24 v1(56.04,27.94)
MIPI_CSI_RX_D2P: length 44.7
  TOP w0.124: U3.47 57.92,28.95 57.8,28.83 57.8,28.69 57.67,28.57 56.34,28.57 v1(56.04,28.87)
  BOTTOM w0.124: v1(56.04,28.87) 55.74,28.57 55.34,28.57 54.91,28.14 54.91,26.77 54.74,26.59 54.2,26.59 53.92,26.87 53.92,29.36 54.05,29.48 54.88,29.48 55.19,29.8 55.19,30.32 54.88,30.64 54.05,30.64 53.92,30.76 53.92,34.9 48.72,40.11 40.14,40.11 38.79,41.46 arc(38.75,41.54) 38.79,41.62 arc(38.82,41.7) 38.79,41.78 38.59,41.97 arc(38.51,42.01) 38.43,41.97 arc(38.35,41.94) 38.27,41.97 38.08,42.17 arc(38.05,42.25) 38.08,42.33 arc(38.12,42.41) 38.08,42.49 37.89,42.68 arc(37.81,42.71) 37.73,42.68 arc(37.65,42.64) 37.57,42.68 36.98,43.27 36.98,47.6 36.69,47.89 36.69,48.52 36.77,48.61 J6.11
MIPI_CSI_RX_D3N: length 44.7
  TOP w0.124: v1(61.92,27.79) 61.62,27.49 61.62,25.38 61.18,24.94 60.48,24.94 60.35,24.82 60.35,24.68 60.23,24.55 U3.43
  BOTTOM w0.124: J6.8 38.27,48.61 38.36,48.52 38.36,47.57 39.18,46.74 39.18,44.43 41.37,42.24 49.11,42.24 56.02,35.33 56.02,33.7 57.29,32.43 57.29,31.08 59.32,29.05 59.32,27.17 59.97,26.52 61.2,26.52 61.62,26.94 61.62,27.49 v1(61.92,27.79)
MIPI_CSI_RX_D3P: length 44.6
  TOP w0.124: v1(60.99,27.79) 61.29,27.49 61.29,25.52 61.04,25.27 60.48,25.27 60.35,25.39 60.35,25.53 60.23,25.66 U3.44
  BOTTOM w0.124: v1(60.99,27.79) 61.04,27.79 61.29,27.54 61.29,27.08 61.06,26.85 60.1,26.85 59.65,27.3 59.65,29.19 57.62,31.22 57.62,32.57 56.35,33.84 56.35,35.46 49.25,42.57 43.86,42.57 arc(43.79,42.6) 43.76,42.67 arc(43.73,42.74) 43.66,42.77 43.37,42.77 arc(43.29,42.74) 43.26,42.67 arc(43.23,42.6) 43.16,42.57 42.87,42.57 arc(42.79,42.6) 42.76,42.67 arc(42.73,42.74) 42.66,42.77 42.37,42.77 arc(42.3,42.74) 42.27,42.67 arc(42.24,42.6) 42.16,42.57 41.51,42.57 41.04,43.04 arc(41,43.12) 41.04,43.2 arc(41.07,43.29) 41.04,43.37 40.85,43.56 arc(40.77,43.59) 40.68,43.56 arc(40.6,43.52) 40.52,43.56 40.33,43.74 arc(40.3,43.82) 40.33,43.91 arc(40.37,43.99) 40.33,44.07 40.14,44.26 arc(40.06,44.29) 39.98,44.26 arc(39.9,44.22) 39.81,44.26 39.51,44.56 39.51,44.92 arc(39.54,45) 39.62,45.03 arc(39.69,45.06) 39.73,45.14 39.73,45.42 arc(39.69,45.49) 39.62,45.53 arc(39.54,45.56) 39.51,45.63 39.51,45.92 arc(39.54,45.99) 39.62,46.02 arc(39.69,46.06) 39.73,46.13 39.73,46.41 arc(39.69,46.49) 39.62,46.52 arc(39.54,46.55) 39.51,46.63 39.51,46.88 38.69,47.7 38.69,48.52 38.77,48.61 J6.7
NPOR: length 84.9
  TOP w0.152: v1(27.51,11.43) 26.48,12.45 U3.119 ; R87.1 74.41,32.81 73.25,31.65 73.25,19.02 72.52,18.29 68.44,18.29 v1(68.18,18.03)
  GND02 w0.152: v1(58.45,6.67) 64.07,12.29 68.15,12.29 68.68,12.83 68.68,17.54 v1(68.18,18.03)
  BOTTOM w0.152: v1(27.51,11.43) 28.96,9.98 44.16,9.98 44.9,10.72 48.86,10.72 50.59,12.45 56.85,12.45 57.15,12.14 57.15,8.38 57.66,7.87 57.66,7.46 v1(58.45,6.67)
PWM3_IR_M1: length 12.3
  TOP w0.152: J12.29 40.01,7.54 39.7,7.85 32.97,7.85 32.66,8.15 32.18,8.15 31.93,8.41 U3.7
PWM7_IR_M1: length 37.9
  TOP w0.152: U3.8 33.03,8.48 33.33,8.18 40.89,8.18 41.2,7.87 41.2,1.65 41.63,1.22 61.84,1.22 J12.12
RGB_LCD_EN: length 108.3
  TOP w0.152: U3.117 24.46,14.66 25.7,15.9 28.2,15.9 28.51,15.6 v1(28.51,11.43) ; v1(77.24,41.45) 77.24,33.57 76.94,33.27 74.08,33.27 72.77,31.95 72.77,19.3 72.26,18.8 68,18.8 67.69,18.49 67.69,17.53 v1(68.18,17.03)
  GND02 w0.152: v1(58.45,7.67) 58.7,7.67 63.8,12.78 67.88,12.78 68.18,13.08 v1(68.18,17.03)
  BOTTOM w0.152: v1(77.24,41.45) 78.08,42.29 78.08,45.64 77.7,46.02 75.13,46.02 73.66,47.5 70.48,47.5 69.98,48.01 R67.1 ; v1(28.51,11.43) 29.5,10.44 43.97,10.44 44.71,11.18 48.67,11.18 50.4,12.9 57.3,12.9 57.61,12.6 57.61,8.57 58.45,7.73 v1(58.45,7.67)
S_SET: length 42.8
  TOP w0.152: SW1.1 63.67,17.83 v1(62.87,17.02)
  BOTTOM w0.152: v1(62.87,17.02) 62.64,17.25 43.59,17.25 42.9,17.93 42.9,25.2 41.58,26.52 41.58,28.75 40.97,29.36 40.97,33.12 40.67,33.43 39.48,33.43 R1.2 38.65,33.82 U1.10
SARADC_IN0_REC: length 74.3
  TOP w0.152: v1(77.84,46.93) 78.49,46.29 78.49,41.25 79.5,40.23 R90.1 ; U3.87 v1(28.63,43.56)
  GND02 w0.152: v1(77.84,46.93) 77.36,47.41 76.39,47.41 75.34,46.35 70.15,46.35 68.44,44.64 65.34,44.64 64.57,43.87 63.02,43.87 62.76,44.12 62.76,44.78 62.48,45.06 59.61,45.06 57.94,46.74 57.94,48.39 56.34,49.99 48.18,49.99 47.88,50.29 47.88,52.04 47.11,52.81 45.17,52.81 44.83,52.48 43.28,52.48 42.77,52.98 34.14,52.98 33.76,52.6 33.76,50.47 33.43,50.14 30.4,50.14 29.36,49.1 29.36,44.3 v1(28.63,43.56)
SARADC_IN1: length 67.1
  TOP w0.152: U3.86 29.73,43.59 v1(29.63,43.49) ; v1(76.84,46.93) 77.45,47.54 79.32,47.54 R91.1
  GND02 w0.152: v1(76.84,46.93) 75.86,45.95 70.43,45.95 68.68,44.2 65.58,44.2 64.82,43.43 62.69,43.43 61.39,44.73 59.41,44.73 56.92,47.22 56.92,48.79 56.16,49.56 47.98,49.56 47.5,50.04 47.5,51.79 46.84,52.45 45.26,52.45 44.86,52.04 43.03,52.04 42.5,52.58 35.1,52.58 34.77,52.25 34.77,50.8 33.73,49.76 30.56,49.76 29.67,48.87 29.67,43.54 v1(29.63,43.49)
SDMMC_CLK: length 46
  TOP w0.157: J2.5 13.62,48.59 12.8,47.78 12.8,47.41 12.96,47.26 13.25,47.26 13.41,47.1 13.41,46.78 13.25,46.63 12.96,46.63 12.8,46.47 12.8,46.15 12.96,46 13.25,46 13.41,45.84 13.41,45.52 13.25,45.37 12.96,45.37 12.8,45.21 12.8,43.28 14.5,41.58 18.84,41.58 D7.1 19.93,42.67 20.4,42.67 21.32,43.6 v1(21.32,44.25) ; U3.78 38.52,43.05 37.34,41.86 35.74,41.86 33.88,40.01 31.01,40.01 30.86,39.85 30.86,39.15 30.67,38.96 30.38,38.96 30.23,39.12 30.23,39.85 30.07,40.01 29.75,40.01 29.6,39.85 29.6,39.15 29.41,38.96 29.12,38.96 28.97,39.12 28.97,39.85 28.81,40.01 28.22,40.01 28.14,40.08 28.14,40.08 v1(27.63,40.59)
  BOTTOM w0.157: v1(27.63,40.59) 28.12,41.07 28.12,41.73 27.79,42.06 26.27,42.06 24,44.32 21.4,44.32 v1(21.32,44.25)
SDMMC_CMD: length 32.9
  TOP w0.157: R18.1 20.44,44.99 20.57,44.86 21.11,44.86 21.29,45.03 21.29,45.72 21.69,46.13 21.69,46.53 21.9,46.74 v1(22.21,46.74) ; v1(25.43,43.66) 25.43,43.21 25.63,43 31.52,43 31.93,43.41 U3.84
  BOTTOM w0.157: v1(22.21,46.74) 22.21,47.06 22.02,47.24 20.95,47.24 20.62,47.57 20.62,49.3 20.47,49.45 20.17,49.45 19.96,49.25 19.96,47.22 20.12,47.07 20.42,47.07 20.57,46.91 20.57,46.59 20.42,46.44 20.07,46.44 19.91,46.28 19.91,45.8 20.14,45.57 20.64,45.57 20.8,45.73 20.8,46.07 20.95,46.23 21.27,46.23 21.43,46.07 21.43,45.73 21.58,45.57 21.87,45.57 22.07,45.77 22.07,46.02 22.23,46.18 22.63,46.18 22.78,46.02 22.78,45.03 22.96,44.86 24.66,44.86 24.82,44.7 24.82,44.25 24.94,44.12 25.25,44.12 25.4,44.27 25.4,44.7 25.55,44.86 25.86,44.86 26.04,44.68 26.04,44.04 25.65,43.66 v1(25.43,43.66)
SDMMC_D0: length 31.8
  TOP w0.157: U3.80 36.33,44 36.11,43.78 35.78,43.78 35.53,43.53 35.53,43.2 35.21,42.89 34.88,42.89 34.64,42.64 34.64,42.31 34.32,41.99 33.99,41.99 33.75,41.75 33.75,41.42 33.45,41.12 29.17,41.12 v1(28.63,40.59) ; v1(21.21,48.01) 21.36,48.16 21.36,48.46 21.2,48.62 20.53,48.62 20.44,48.53 R19.1
  BOTTOM w0.157: v1(21.21,48.01) 21.13,48.08 21.13,48.41 21.29,48.56 21.56,48.56 21.74,48.39 21.74,47.9 21.89,47.75 22.07,47.75 22.2,47.88 22.2,48.18 22.33,48.31 22.58,48.31 22.73,48.15 22.73,46.74 23.27,46.2 23.27,45.59 23.44,45.42 23.73,45.42 23.89,45.57 23.89,45.97 24.04,46.13 24.36,46.13 24.52,45.97 24.52,45.57 24.67,45.42 25.98,45.42 27.03,44.37 27.03,43.24 26.87,43.08 26.49,43.08 26.32,42.9 26.32,42.68 26.47,42.52 27.05,42.52 27.28,42.75 27.73,42.75 27.96,42.52 28.24,42.52 28.59,42.18 28.59,41.78 28.71,41.66 29.16,41.66 29.36,41.45 29.36,41.17 29.24,41.05 28.73,41.05 28.59,40.91 28.59,40.63 v1(28.63,40.59)
SDMMC_D1: length 21.5
  TOP w0.157: v1(27.6,41.57) 27.61,41.57 27.63,41.58 32.85,41.58 35.22,43.96 U3.81 ; v1(20.2,42.17) 20.2,40.27 R20.1
  BOTTOM w0.157: v1(20.2,42.17) 20.2,42.22 20.78,42.8 23.52,42.8 24.18,42.14 24.18,41.99 25.22,40.94 26.97,40.94 27.59,41.57 v1(27.6,41.57)
SDMMC_D2: length 30.1
  TOP w0.157: R16.1 v1(18.68,43.17) ; v1(26.51,41.48) 27.09,42.06 32.54,42.06 34.12,43.65 U3.82
  BOTTOM w0.157: v1(18.68,43.17) 16.87,43.17 16.71,43.33 16.71,43.59 16.87,43.75 17.72,43.75 17.88,43.91 17.88,44.22 17.72,44.38 16.9,44.38 16.71,44.56 16.71,46.04 17.03,46.35 17.88,46.35 18.03,46.2 18.03,44.93 18.14,44.83 19.18,44.83 19.43,44.58 20.19,44.58 21.01,43.76 23.91,43.76 26.19,41.48 v1(26.51,41.48)
SDMMC_D3: length 35
  TOP w0.157: U3.83 33.03,43.64 31.92,42.54 25.67,42.54 25.41,42.27 v1(25.41,41.48) ; v1(20.19,43.16) 20.19,43.17 20.44,43.41 R17.1
  BOTTOM w0.157: v1(20.19,43.16) 20.19,43 19.58,42.39 19.58,41.18 19.43,41.02 19.19,41.02 19.03,41.18 19.03,41.98 18.85,42.16 18.56,42.16 18.4,42.01 18.4,41.23 18.2,41.02 17.86,41.02 17.63,40.79 17.63,39.78 17.47,39.62 16.89,39.62 16.74,39.78 16.74,42.54 16.9,42.7 17.17,42.7 17.33,42.54 17.33,41.94 17.49,41.78 17.8,41.78 17.96,41.94 17.96,42.51 18.12,42.67 19.02,42.67 19.18,42.83 19.18,43.81 19.41,44.04 20.07,44.04 20.85,43.26 23.71,43.26 25.41,41.56 v1(25.41,41.48)
SDMMC_DET: length 29.8
  TOP w0.157: v1(29.61,40.59) 33.73,40.59 35.48,42.34 37.16,42.34 37.34,42.52 37.34,42.77 37.18,42.93 36.46,42.93 36.37,43.01 36.37,43.29 36.56,43.48 37.14,43.48 37.43,43.76 U3.79 ; v1(21.21,49.15) 21.21,49.88 21.05,50.04 20.58,50.04 20.44,49.9 R21.1
  BOTTOM w0.157: v1(21.21,49.15) 21.31,49.25 21.54,49.25 21.89,48.9 23.04,48.9 23.24,48.69 23.24,46.89 23.52,46.61 24.92,46.61 25.07,46.46 25.07,46.02 25.17,45.92 26.29,45.92 28.09,44.12 28.09,43.38 29.87,41.61 29.87,40.85 v1(29.61,40.59)
SIM_CLK0: length 29.5
  TOP w0.157: R54.1 18.35,39.49 v1(18.69,39.14)
  BOTTOM w0.157: v1(18.69,39.14) 19.25,39.7 23.42,39.7 24.12,39 24.12,26.59 27.57,23.14 27.57,20.33 28.49,19.41 J4.12
SIM_DATA0: length 32.5
  TOP w0.152: v1(18.77,35.46) 18.92,35.31 R56.1
  BOTTOM w0.152: J4.10 28.45,18.61 27.08,19.99 27.08,22.86 23.62,26.31 23.62,38.81 23.19,39.24 19.68,39.24 19.23,38.79 19.23,35.86 18.83,35.46 v1(18.77,35.46)
SIM_RST0: length 42.4
  TOP w0.152: R55.1 18.16,32.99 20.12,31.04 v1(20.12,30.81)
  BOTTOM w0.152: v1(20.12,30.81) 18.97,30.81 18.01,31.78 18.01,39.14 19.03,40.16 23.67,40.16 24.58,39.25 24.58,26.93 28.07,23.44 28.07,20.55 28.4,20.21 J4.14
SIM_VDD: length 63.5
  TOP w0.305: 19.41,33.16 19.37,33.16 18.77,33.76 18.77,34.63 18.2,35.19 U12.1 17.64,35.82 17.42,35.61 v1(17.42,35.2) ; 19.41,33.16 R53.1 ; 19.41,33.16 v1(19.41,32.46)
  BOTTOM w0.305: v1(17.42,35.2) 17.42,36.68 16.89,37.21 9.91,37.21 9.37,37.74 9.37,46.05 9.9,46.57 J14.1 ; J4.8 28.37,17.81 26.67,19.51 26.67,22.5 23.06,26.11 23.06,38.48 22.71,38.84 20.19,38.84 19.76,38.4 19.76,35.38 19.15,34.77 19.15,32.72 v1(19.41,32.46)
SPI1_CLK_M0: length 47.6
  TOP w0.157: v1(38,3.28) 38,6.26 37.56,6.71 32.15,6.71 31.88,6.97 30.89,6.97 30.54,7.32 27.14,7.32 26.66,7.8 24.76,7.8 23.74,8.81 21.98,8.81 21.66,9.13 21.66,23.34 22.07,23.75 22.07,24.23 22.4,24.55 U3.108
  BOTTOM w0.157: J12.23 46.72,4.79 45.69,3.75 38.48,3.75 v1(38,3.28)
SPI1_CS0_M0: length 47.8
  TOP w0.152: v1(38,2.28) 38.48,2.76 38.48,6.86 38.18,7.17 32.43,7.17 32.16,7.43 31.08,7.43 30.73,7.78 27.46,7.78 26.97,8.26 24.95,8.26 23.93,9.27 22.43,9.27 22.12,9.58 22.12,23.15 22.43,23.46 U3.109
  BOTTOM w0.152: v1(38,2.28) 39.08,1.19 46.57,1.19 J12.24
SPI1_MISO_M0: length 54.8
  TOP w0.152: v1(33.48,5.54) 33.12,5.89 31.77,5.89 31.45,6.21 30.31,6.21 30,6.53 26.77,6.53 26.34,6.96 21.21,6.96 20.85,7.32 20.85,23.62 21.18,23.95 21.18,25.91 22.03,26.76 U3.106
  BOTTOM w0.152: J12.21 49.26,4.79 48.23,3.76 46.76,3.76 46.28,3.27 39.29,3.27 38.79,2.77 36.58,2.77 36.27,3.07 36.27,5.36 35.97,5.66 33.6,5.66 v1(33.48,5.54)
SPI1_MOSI_M0: length 59.5
  TOP w0.152: v1(37,3.28) 37.41,3.69 37.41,5.94 37.11,6.25 31.96,6.25 31.69,6.52 30.54,6.52 30.2,6.86 26.95,6.86 26.47,7.34 21.46,7.34 21.16,7.65 21.16,23.49 21.59,23.92 21.59,25.2 22.05,25.66 U3.107
  GND02 w0.152: v1(37,3.28) 37,1.93 37.71,1.22 50.95,1.22 51.26,1.52 51.26,3.34 J12.19
SPK_CTRL: length 44.4
  TOP w0.152: U17.1 62.99,39.88 63.65,39.22 63.65,37.44 63.88,37.21 65.41,37.21 65.66,36.96 65.66,34.29 66.04,33.91 67.41,33.91 67.72,33.6 67.72,23.97 v1(67.01,23.27)
  BOTTOM w0.152: v1(67.01,23.27) 67.01,21.62 66.68,21.29 52.5,21.29 51.71,20.49 47.61,20.49 47.46,20.64 U5.8
SYS_LED: length 49
  TOP w0.152: v1(51.7,11.18) 50.37,12.51 50.37,21.93 v1(50.58,22.14)
  BOTTOM w0.152: v1(51.7,11.18) 52.18,11.66 52.99,11.66 53.22,11.42 53.22,10.72 53.43,10.5 54.58,10.5 54.99,10.1 54.99,6.73 53.87,5.61 53.87,3.91 53.62,3.66 51.77,3.66 51.38,3.27 49.43,3.27 49.05,2.9 49.05,1.47 48.44,0.86 38.33,0.86 37.74,1.45 35.79,1.45 35.48,1.75 35.48,3.64 35.18,3.95 R11.1 ; v1(50.58,22.14) 50.08,22.64 U5.5
UART2_DBG_RX: length 89
  TOP w0.152: U3.9 v1(34.12,11.23) ; R89.2 71.28,45.31 72.75,45.31 73.15,44.91 73.15,42.67 73.63,42.19 75.97,42.19 76.28,41.88 76.28,34.49 75.97,34.19 73.58,34.19 71.75,32.36 71.75,19.84 71.6,19.68 67.18,19.68 66.67,19.18 66.67,17.54 v1(67.18,17.03)
  GND02 w0.152: v1(67.18,17.03) 67.18,13.94 66.95,13.72 63.58,13.72 60.02,10.16 58.09,10.16 57.81,9.88 57.81,8.92 58.06,8.67 v1(58.45,8.67)
  BOTTOM w0.152: v1(34.12,11.23) 34.61,10.74 43.59,10.74 44.53,11.68 48.69,11.68 50.22,13.21 57.63,13.21 57.94,12.9 57.94,9.18 v1(58.45,8.67)
UART2_DBG_TX: length 81.8
  TOP w0.152: U3.10 v1(35.22,11.23) ; R88.2 78.03,45.66 78.03,43.23 76.73,41.94 76.73,34.04 76.43,33.73 73.79,33.73 72.26,32.21 72.26,19.56 72.01,19.3 67.56,19.3 67.18,18.92 v1(67.18,18.03)
  GND02 w0.152: v1(67.18,18.03) 67.69,17.53 67.69,13.82 67.13,13.26 63.75,13.26 60.17,9.67 v1(58.45,9.67)
  BOTTOM w0.152: v1(35.22,11.23) 43.43,11.23 44.42,12.22 48.76,12.22 50.06,13.51 58.14,13.51 58.45,13.21 v1(58.45,9.67)
UART3_RX_M0: length 46.1
  TOP w0.152: U3.3 27.52,8.43 27.83,8.13 30.94,8.13 31.29,7.77 32.44,7.77 32.69,7.52 38.56,7.52 38.86,7.21 38.86,1.27 39.22,0.91 61.96,0.91 61.96,0.91 64.07,0.91 J12.10
UART3_TX_M0: length 56.1
  TOP w0.152: U3.2 v1(26.42,11.43)
  BOTTOM w0.152: J12.8 66.92,1.22 57.02,1.22 56.67,1.57 56.67,11.68 56.36,11.99 50.77,11.99 49.05,10.26 45.11,10.26 44.37,9.53 28.33,9.53 v1(26.42,11.43)
USB_4G_DM3: length 17.5
  TOP w0.157: v1(34.22,32.13) 34.22,32.31 34.07,32.47 33.49,32.47 33.18,32.15 33.18,31.74 arc(33.23,31.62) 33.35,31.57 arc(33.48,31.52) 33.53,31.39 33.53,31.11 arc(33.48,30.99) 33.35,30.94 arc(33.23,30.89) 33.18,30.76 33.18,30.37 33.71,29.84 arc(33.82,29.79) 33.93,29.84 arc(34.04,29.88) 34.14,29.84 34.37,29.61 arc(34.42,29.5) 34.37,29.39 arc(34.33,29.28) 34.37,29.18 34.95,28.6 34.95,21.56 35.11,21.4 v1(35.26,21.4)
  BOTTOM w0.157: U6.7 35.4,22.14 35.33,22.21 35.11,22.21 34.95,22.06 34.95,21.56 35.11,21.4 v1(35.26,21.4) ; R57.2 33.47,32.44 34.07,32.44 34.22,32.28 v1(34.22,32.13)
USB_4G_DP3: length 17.5
  TOP w0.157: v1(34.29,21.4) 34.59,21.7 34.59,28.45 32.82,30.22 32.82,32.3 33.34,32.83 33.96,32.83 v1(34.22,33.1)
  BOTTOM w0.157: R58.2 33.43,32.83 33.45,32.83 33.48,32.8 33.93,32.8 v1(34.22,33.1) ; U6.8 35.4,22.64 35.33,22.57 34.96,22.57 34.59,22.21 34.59,21.7 v1(34.29,21.4)
USB_DM1: length 42.3
  TOP w0.157: v1(17.5,24.25) 17.2,24.55 17.2,25.76 17.53,26.09 R37.2
  BOTTOM w0.157: U6.11 35.4,24.14 35.33,24.21 33.46,24.21 32.57,23.32 32.57,15.32 31.47,14.22 28.31,14.22 27.79,14.75 27.79,15.93 24.66,19.05 24.66,22.07 23.9,22.83 16.59,22.83 15.7,23.72 15.7,25.03 16.07,25.4 16.83,25.4 17.2,25.03 17.2,24.55 v1(17.5,24.25)
USB_DM2: length 49.1
  TOP w0.157: R40.2 19.56,26.09 19.23,25.76 19.23,24.58 v1(19.53,24.28)
  BOTTOM w0.157: U6.9 35.4,23.14 35.33,23.21 34.44,23.21 33.68,22.45 33.68,14.88 32.08,13.28 27.28,13.28 26.76,13.81 26.76,15.46 23.44,18.77 23.44,21.13 23.04,21.53 16.24,21.53 14.73,23.04 14.73,26.21 15.38,26.86 18.4,26.86 19.23,26.03 19.23,24.58 v1(19.53,24.28)
USB_DP1: length 42.3
  TOP w0.157: R38.2 16.51,26.09 16.84,25.76 16.84,24.55 v1(16.54,24.25)
  BOTTOM w0.157: v1(16.54,24.25) 16.66,24.25 16.84,24.43 16.84,24.88 16.68,25.04 16.22,25.04 16.06,24.88 16.06,23.87 16.74,23.19 17.07,23.19 arc(17.18,23.23) 17.22,23.34 arc(17.27,23.45) 17.38,23.5 17.7,23.5 arc(17.81,23.45) 17.85,23.34 arc(17.9,23.23) 18.01,23.19 18.33,23.19 arc(18.44,23.23) 18.48,23.34 arc(18.53,23.45) 18.64,23.5 18.96,23.5 arc(19.07,23.45) 19.11,23.34 arc(19.16,23.23) 19.27,23.19 19.59,23.19 arc(19.7,23.23) 19.74,23.34 arc(19.79,23.45) 19.9,23.5 20.22,23.5 arc(20.33,23.45) 20.37,23.34 arc(20.42,23.23) 20.53,23.19 20.85,23.19 arc(20.96,23.23) 21,23.34 arc(21.05,23.45) 21.16,23.5 21.48,23.5 arc(21.59,23.45) 21.63,23.34 arc(21.68,23.23) 21.79,23.19 22.11,23.19 arc(22.22,23.23) 22.26,23.34 arc(22.31,23.45) 22.42,23.5 22.74,23.5 arc(22.85,23.45) 22.89,23.34 arc(22.94,23.23) 23.05,23.19 24.05,23.19 25.02,22.22 25.02,19.2 28.15,16.08 28.15,14.9 28.46,14.58 31.32,14.58 32.21,15.47 32.21,23.47 33.31,24.57 35.33,24.57 35.4,24.64 U6.12
USB_DP2: length 49.6
  TOP w0.157: R42.2 18.54,26.09 18.87,25.76 18.87,24.58 v1(18.57,24.28)
  BOTTOM w0.157: U6.10 35.4,23.64 35.33,23.57 34.29,23.57 33.32,22.6 33.32,15.03 31.93,13.64 27.43,13.64 27.12,13.96 27.12,15.61 23.8,18.92 23.8,21.28 23.19,21.89 22.71,21.89 arc(22.61,21.94) 22.57,22.03 arc(22.53,22.13) 22.43,22.17 22.08,22.17 arc(21.98,22.13) 21.94,22.03 arc(21.9,21.94) 21.8,21.89 21.45,21.89 arc(21.35,21.94) 21.31,22.03 arc(21.27,22.13) 21.17,22.17 20.82,22.17 arc(20.72,22.13) 20.68,22.03 arc(20.64,21.94) 20.54,21.89 20.19,21.89 arc(20.09,21.94) 20.05,22.03 arc(20.01,22.13) 19.91,22.17 19.56,22.17 arc(19.46,22.13) 19.42,22.03 arc(19.38,21.94) 19.28,21.89 18.93,21.89 arc(18.83,21.94) 18.79,22.03 arc(18.75,22.13) 18.65,22.17 18.3,22.17 arc(18.2,22.13) 18.16,22.03 arc(18.12,21.94) 18.02,21.89 17.67,21.89 arc(17.57,21.94) 17.53,22.03 arc(17.49,22.13) 17.39,22.17 17.04,22.17 arc(16.94,22.13) 16.9,22.03 arc(16.86,21.94) 16.76,21.89 16.39,21.89 15.09,23.19 15.09,26.06 15.53,26.5 15.82,26.5 arc(15.91,26.46) 15.95,26.37 arc(15.99,26.28) 16.08,26.24 16.45,26.24 arc(16.54,26.28) 16.58,26.37 arc(16.62,26.46) 16.71,26.5 17.08,26.5 arc(17.17,26.46) 17.21,26.37 arc(17.25,26.28) 17.34,26.24 17.71,26.24 arc(17.8,26.28) 17.84,26.37 arc(17.88,26.46) 17.97,26.5 18.25,26.5 18.87,25.89 18.87,24.44 18.71,24.28 v1(18.57,24.28)
USB_HOST_EN: length 83.7
  TOP w0.152: v1(49.58,21.14) 49.58,12.3 v1(50.7,11.18)
  BOTTOM w0.152: v1(49.58,21.14) 49.44,21.01 48.11,21.01 47.96,21.16 U5.7 ; U7.4 1.82,31.03 1.27,30.48 1.27,28.53 1.82,27.98 U8.4 1.82,26.67 1.24,26.09 1.24,23.4 R47.1 2.29,20.36 2.72,19.94 19.02,19.94 19.48,19.48 19.48,11.05 19.79,10.74 24.49,10.74 26.06,9.17 44.7,9.17 45.29,9.75 49.28,9.75 v1(50.7,11.18)
USB_HUB_DM: length 7.7
  BOTTOM w0.157: U6.14 37.5,26.24 37.57,26.31 37.57,29.43 37.39,29.62 37.11,29.62 36.86,29.87 36.86,30.3 arc(36.81,30.41) 36.7,30.45 arc(36.6,30.5) 36.55,30.61 36.55,30.93 arc(36.6,31.04) 36.7,31.08 arc(36.81,31.13) 36.86,31.24 36.86,31.52 36.99,31.65 U1.6
USB_HUB_DP: length 7.8
  BOTTOM w0.157: U6.15 38,26.24 37.93,26.31 37.93,29.17 38.33,29.57 39.09,29.57 39.55,30.02 39.55,31.34 39.24,31.65 U1.2
USB_RV_DM: length 27.4
  TOP w0.157: v1(37.45,30.23) 38.09,29.59 38.09,29.35 37.78,29.04 36.29,29.04 35.82,29.51 35.82,29.83 arc(35.86,29.92) 35.96,29.96 arc(36.05,30) 36.09,30.1 36.09,30.46 arc(36.05,30.55) 35.96,30.59 arc(35.86,30.63) 35.82,30.73 35.82,31.09 arc(35.86,31.18) 35.96,31.22 arc(36.05,31.26) 36.09,31.36 36.09,31.71 arc(36.05,31.81) 35.96,31.85 arc(35.86,31.89) 35.82,31.99 35.82,33.75 34.59,34.98 27.85,34.98 27.53,35.29 27.53,39.5 26.35,40.69 25,40.69 24.63,41.06 U3.93
  BOTTOM w0.157: U1.5 37.85,30.63 v1(37.45,30.23)
USB_RV_DP: length 27.4
  TOP w0.157: U3.94 24.63,39.95 25,40.32 26.2,40.32 27.17,39.35 27.17,35.14 27.7,34.62 34.45,34.62 35.46,33.6 35.46,29.36 36.14,28.68 37.93,28.68 38.45,29.2 38.45,29.63 v1(39.05,30.23)
  BOTTOM w0.157: U1.3 38.65,30.63 v1(39.05,30.23)
USB_VBUS0: length 9.8
  BOTTOM w0.762: J3.1 12.14,33.17 8.69,33.17 7.65,32.13 7.65,30.4 6.76,29.51
USB_VBUS1: length 9.1
  BOTTOM w0.762: J3.7 9.04,30.35 9.04,26.44 7.37,24.77 6.58,24.77
USB_VBUSDET: length 10.9
  TOP w0.152: U3.91 22.25,43.25 22.02,43.48 22.02,43.92 22.23,44.12 v1(22.23,45.2)
  BOTTOM w0.152: v1(22.23,45.2) 22.11,45.09 19.81,45.09 19.43,45.47 R7.1 19.42,48.01 18.92,48.51 18.41,48.51 R6.2
USB_WLAN_DM4: length 58.7
  TOP w0.157: v1(70.79,25.78) 70.52,25.5 70.52,21.91 69.53,20.92 63.52,20.92 62.79,20.19 62.79,18.18 61.88,17.28 61.88,15.6 62.04,15.44 62.36,15.44 v1(62.58,15.67)
  BOTTOM w0.157: R49.1 69.16,28.07 69.49,27.74 69.97,27.74 70.49,27.22 70.49,26.08 v1(70.79,25.78) ; U6.5 37.5,20.88 37.42,20.79 37.42,20.43 37.03,20.04 35.79,20.04 35.18,19.43 35.18,19.14 arc(35.22,19.04) 35.32,19 arc(35.42,18.96) 35.46,18.86 35.46,18.51 arc(35.42,18.41) 35.32,18.37 arc(35.22,18.33) 35.18,18.23 35.18,17.88 arc(35.22,17.78) 35.32,17.74 arc(35.42,17.7) 35.46,17.6 35.46,17.25 arc(35.42,17.15) 35.32,17.11 arc(35.22,17.07) 35.18,16.97 35.18,15.37 35.51,15.04 41.5,15.04 42.75,16.29 60.91,16.29 61.74,15.46 62.37,15.46 v1(62.58,15.67)
USB_WLAN_DP4: length 58.8
  TOP w0.157: v1(69.83,25.78) 70.15,25.45 70.15,22.06 69.38,21.29 63.37,21.29 62.43,20.34 62.43,18.33 61.52,17.42 61.52,15.45 61.89,15.08 62.21,15.08 v1(62.58,14.7)
  BOTTOM w0.157: U6.6 37,20.86 37.06,20.8 37.06,20.58 36.88,20.4 35.64,20.4 34.82,19.58 34.82,15.22 35.36,14.68 41.65,14.68 42.9,15.93 60.76,15.93 61.59,15.09 62.19,15.09 v1(62.58,14.7) ; R50.1 69.16,27.05 69.49,27.38 69.82,27.38 70.13,27.07 70.13,26.08 v1(69.83,25.78)
VO_LCDC_CLK: length 38.8
  TOP w0.157: U3.12 37.43,10.96 38.28,11.81 38.28,21.38 37.96,21.69 36.75,21.69 36.22,22.23 v1(36.22,26.26)
  BOTTOM w0.157: v1(36.22,26.26) 35.03,27.46 35.03,28.57 35.94,29.49 35.94,34.67 37.31,36.04 37.31,37.81 36.91,38.21 36.91,38.72 33.78,41.85 R95.1
VO_LCDC_D0: length 76.4
  TOP w0.152: v1(34.91,36.48) 34.91,36.01 35.38,35.53 36.55,35.53 36.98,35.97 36.98,38.3 37.77,39.09 40.46,39.09 41.53,38.02 41.53,30.73 41.07,30.28 41.07,23.6 42.47,22.2 42.47,11.33 41.82,10.68 U3.16 ; v1(38.02,52.02) 37.52,51.52 J7.17
  BOTTOM w0.152: v1(34.91,36.48) 34.39,37 34.39,38.23 31.72,40.89 31.72,44.08 30.87,44.93 29.77,44.93 28.47,46.23 28.47,49.17 27.13,50.52 27.13,53.49 27.69,54.05 37.71,54.05 38.02,53.75 v1(38.02,52.02)
VO_LCDC_D1: length 73.8
  TOP w0.152: J7.16 37.02,51.51 v1(36.52,52.01) ; v1(34.91,37.48) 34.91,37.18 35.39,36.69 35.39,36.22 35.7,35.91 36.27,35.91 36.58,36.22 36.58,38.58 37.53,39.53 40.65,39.53 41.86,38.33 41.86,30.48 41.45,30.07 41.45,23.93 42.92,22.45 U3.17
  BOTTOM w0.152: v1(36.52,52.01) 36.52,53.44 36.21,53.75 27.81,53.75 27.43,53.37 27.43,50.72 28.85,49.3 28.85,46.32 29.94,45.24 31,45.24 32.03,44.21 32.03,41.05 34.91,38.17 v1(34.91,37.48)
VO_LCDC_D2: length 64.1
  TOP w0.152: U3.18 44.03,10.84 43.38,11.48 43.38,22.68 41.94,24.13 41.94,30 42.21,30.28 42.21,38.61 40.88,39.94 37.25,39.94 35.91,38.6 v1(35.91,37.43) ; J7.15 v1(36.52,51.01)
  BOTTOM w0.152: v1(35.91,37.43) 35.73,37.61 35.73,38.26 32.64,41.35 32.64,44.55 31.29,45.9 30.23,45.9 29.49,46.63 29.49,50.27 31.19,51.97 34.82,51.97 35.3,51.49 35.74,51.49 36.22,51.01 v1(36.52,51.01)
VO_LCDC_D3: length 69
  TOP w0.152: U3.19 45.12,10.7 43.92,11.91 43.92,24.59 42.47,26.04 42.47,29.54 43.26,30.33 43.26,38.2 41.11,40.35 36.97,40.35 35.43,38.8 35.43,37.22 35.91,36.74 v1(35.91,36.48) ; J7.14 36.02,51.51 v1(35.52,52.01)
  BOTTOM w0.152: v1(35.52,52.01) 35.12,52.4 31.19,52.4 29.18,50.39 29.18,46.46 30.05,45.59 31.08,45.59 32.33,44.34 32.33,41.17 35.41,38.1 35.41,36.98 v1(35.91,36.48)
VO_LCDC_D4: length 71.6
  TOP w0.152: J7.13 v1(35.52,51.01) ; v1(33.91,36.48) 34.43,37 34.43,38.49 36.69,40.75 41.39,40.75 43.56,38.58 43.56,29.97 42.93,29.34 42.93,26.21 44.48,24.66 44.48,12.55 46.22,10.8 U3.20
  BOTTOM w0.152: v1(33.91,36.48) 34.45,35.94 36.05,35.94 36.39,36.28 36.39,37.63 36.04,37.97 36.04,38.46 32.94,41.55 32.94,44.7 31.45,46.2 30.35,46.2 29.82,46.74 29.82,50.14 31.22,51.54 34.59,51.54 35.13,51.01 v1(35.52,51.01)
VO_LCDC_D5: length 71.1
  TOP w0.152: U3.21 47.33,10.69 44.98,13.03 44.98,24.87 43.97,25.88 43.97,38.94 41.76,41.15 36.45,41.15 33.91,38.61 v1(33.91,37.48) ; v1(30.41,46.85) 30.88,46.38 34.42,46.38 35.02,46.98 J7.12
  BOTTOM w0.152: v1(33.91,37.48) 33.43,37 33.43,36.27 34.14,35.56 36.18,35.56 36.83,36.21 36.83,37.64 36.42,38.05 36.42,38.56 33.27,41.71 33.27,41.76 33.25,41.78 33.25,44.91 31.3,46.85 v1(30.41,46.85)
VO_LCDC_D6: length 72.1
  TOP w0.152: U3.22 48.43,10.91 46.19,13.14 46.19,24.85 45.59,25.45 45.59,33.27 44.57,34.29 v1(44.57,37.44) ; v1(41.02,52.02) 41.02,51.74 41.52,51.24 J7.25
  GND02 w0.152: v1(44.57,37.44) 45.06,36.96 48.13,36.96 48.62,37.44 54.99,37.44 55.61,38.06 55.61,40.68 55.24,41.05 54.38,41.05 54.23,40.89 54.23,40.31 53.92,40.01 48.64,40.01 46.91,41.73 46.91,45.67 46.61,45.97 41.83,45.97 41.53,46.28 41.53,51.51 v1(41.02,52.02)
VO_LCDC_D7: length 68.1
  TOP w0.152: J7.24 v1(41.02,51.02) ; U3.23 49.52,10.75 47.52,12.75 47.52,21.69 47.19,22.02 47.19,24.77 45.92,26.04 45.92,33.63 45.03,34.52 45.03,36.37 45.57,36.91 v1(45.57,37.44)
  GND02 w0.152: v1(41.02,51.02) 41.1,50.95 41.1,45.8 41.4,45.49 45.39,45.49 45.69,45.19 45.69,40.03 46.2,39.52 54,39.52 54.52,40.04 55.07,40.04 55.22,39.89 55.22,38.25 54.89,37.92 46.06,37.92 v1(45.57,37.44)
VO_LCDC_D8: length 53.4
  TOP w0.152: J7.23 40.52,51.52 v1(40.02,52.02) ; v1(27.58,27.96) 27.48,27.85 U3.105
  BOTTOM w0.152: v1(27.58,27.96) 28.07,28.44 28.07,38.96 28.29,39.19 30.86,39.19 31.42,39.75 31.42,43.87 31.41,43.87 31.41,43.89 30.7,44.6 29.67,44.6 28.12,46.15 28.12,49 26.82,50.29 26.82,53.62 27.56,54.36 39.71,54.36 40.02,54.05 v1(40.02,52.02)
